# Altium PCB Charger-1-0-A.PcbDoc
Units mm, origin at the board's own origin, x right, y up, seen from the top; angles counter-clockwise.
Board outline 99.95 x 99.95 mm, 4 copper layers (Top Layer, Top GND, Bottom GND, Bottom Layer), stack 1.376 mm thick; 84 components, 44 nets, 253 pads, 194 vias.
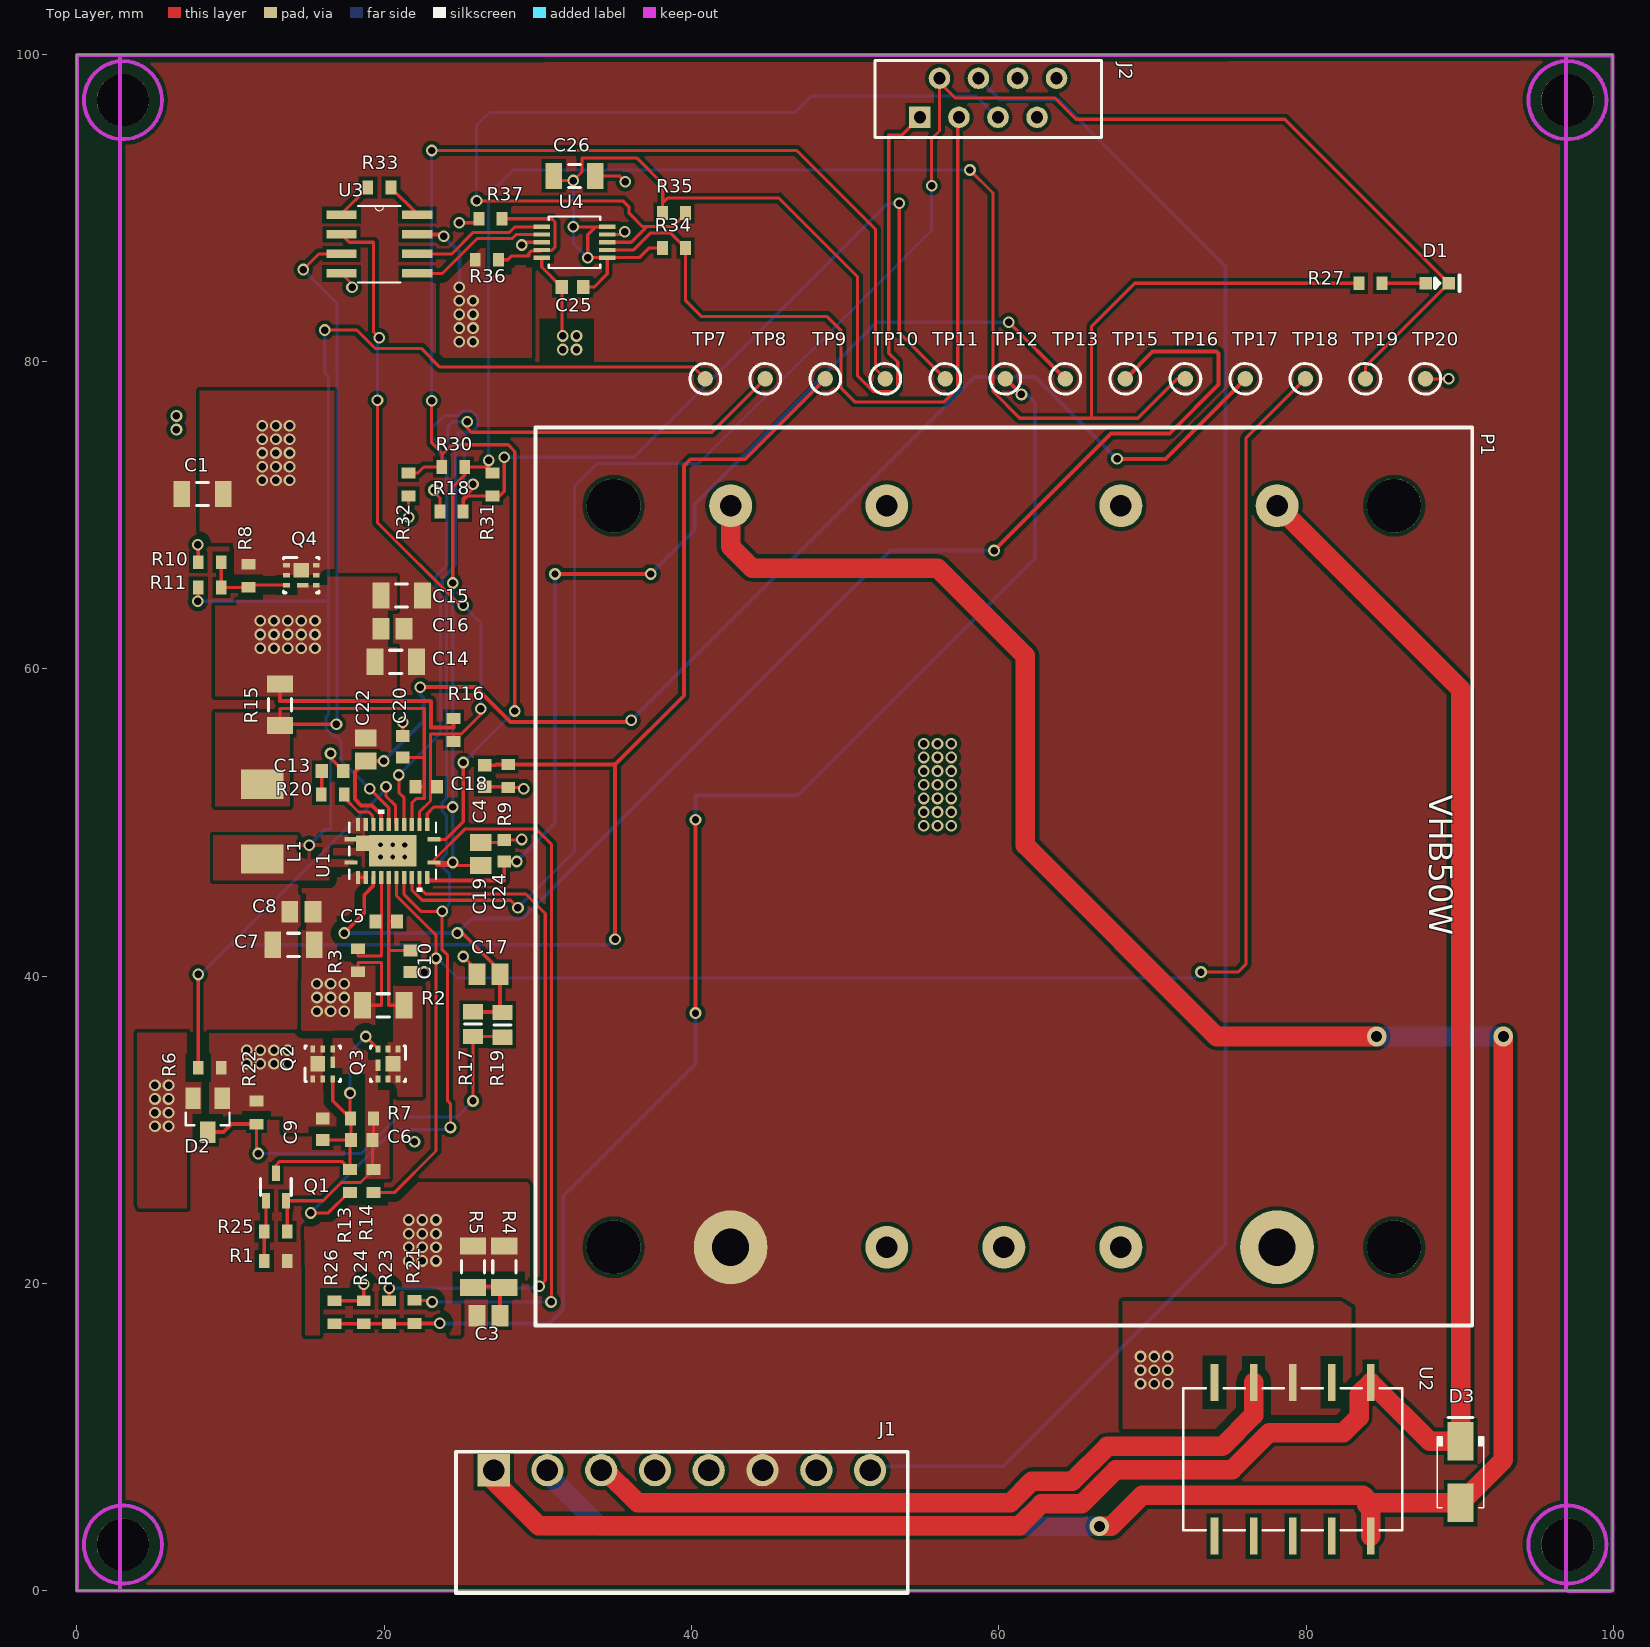
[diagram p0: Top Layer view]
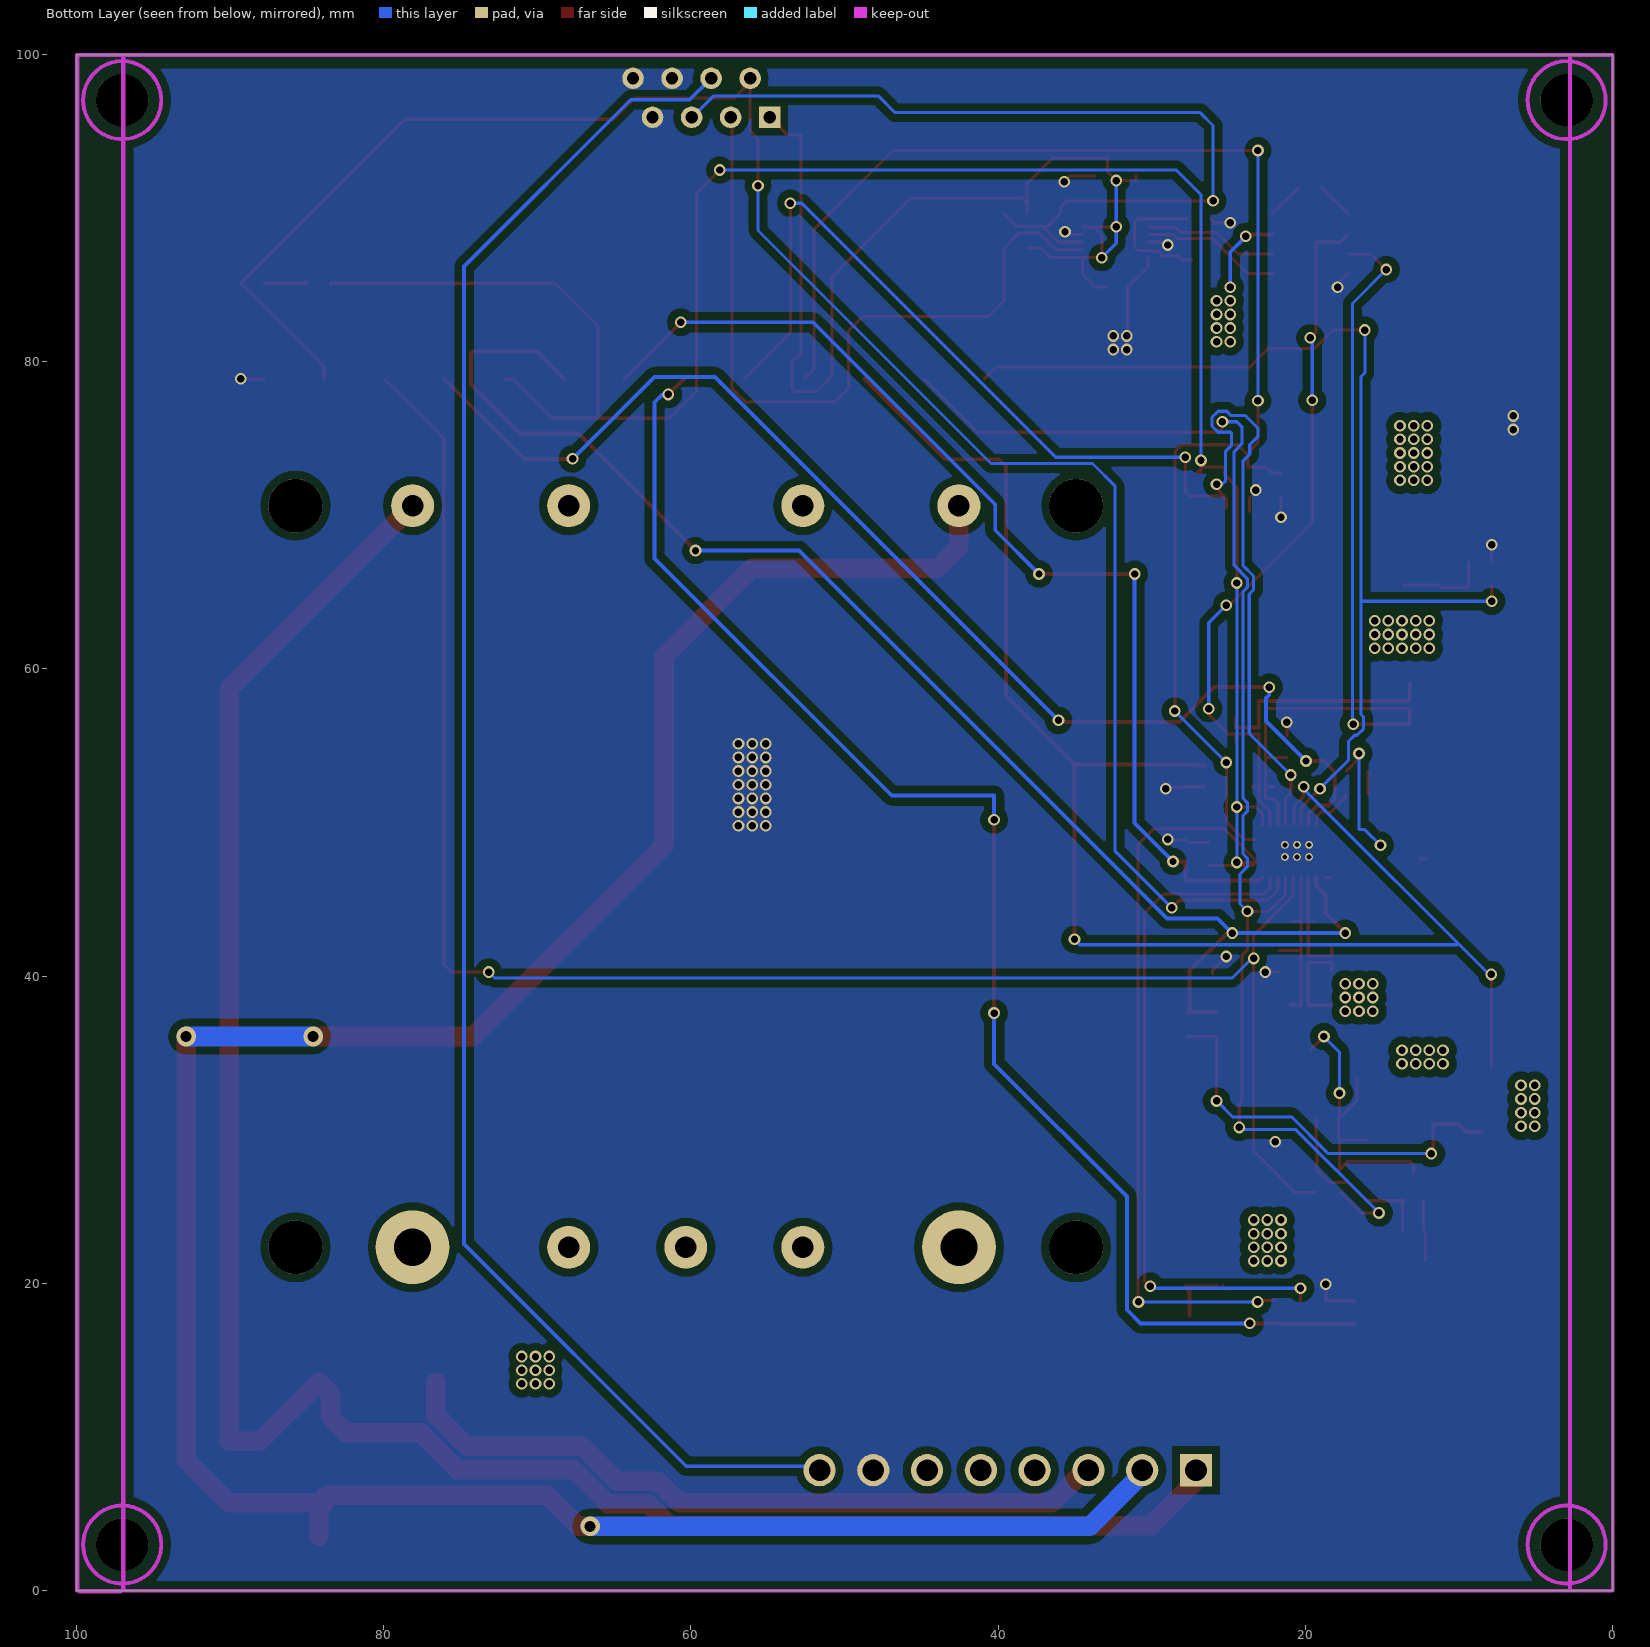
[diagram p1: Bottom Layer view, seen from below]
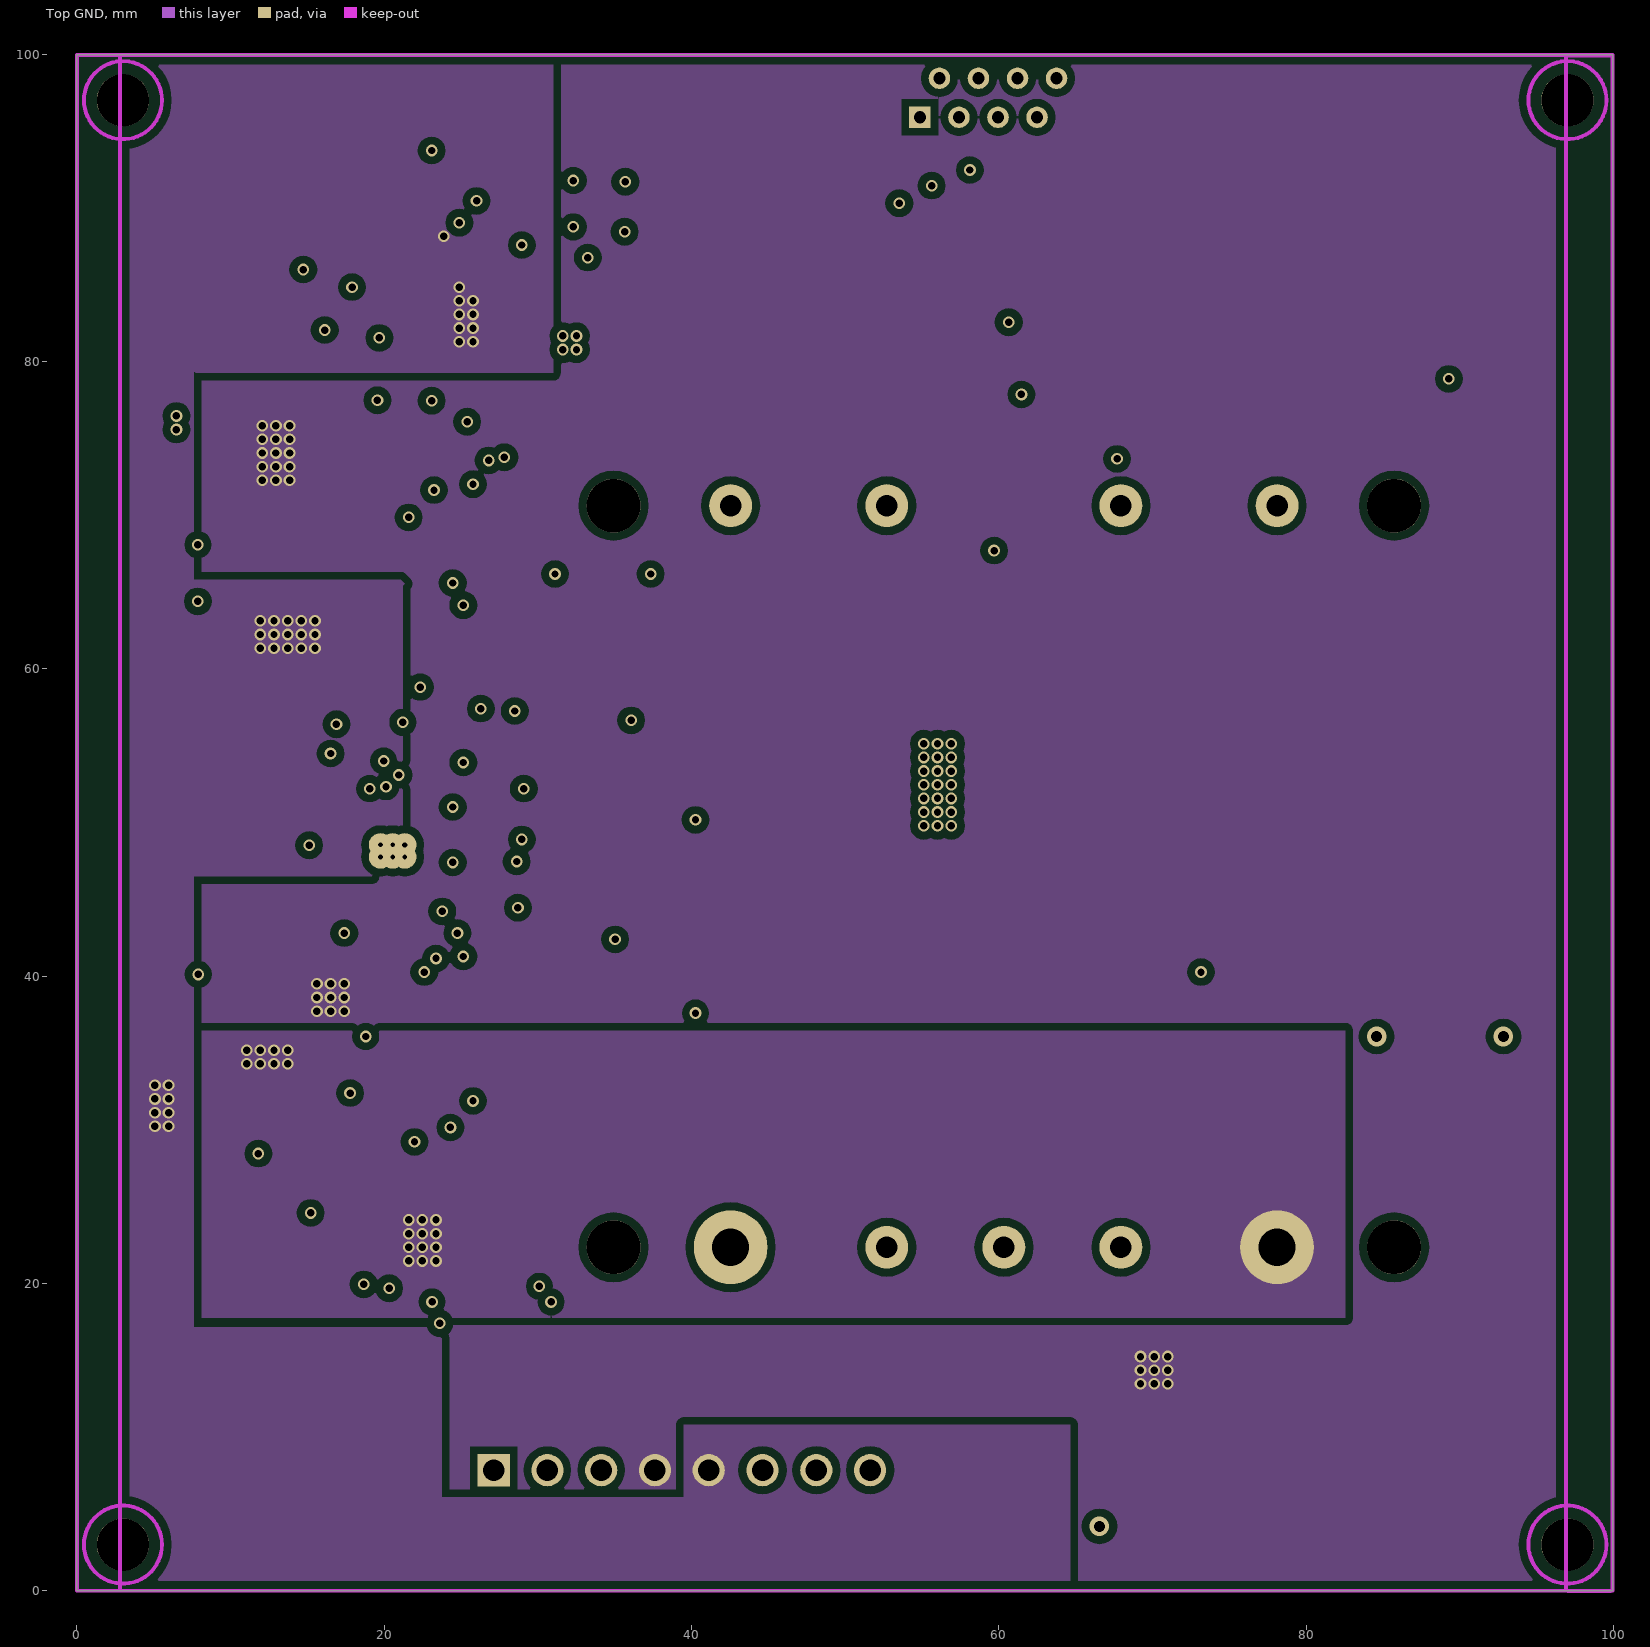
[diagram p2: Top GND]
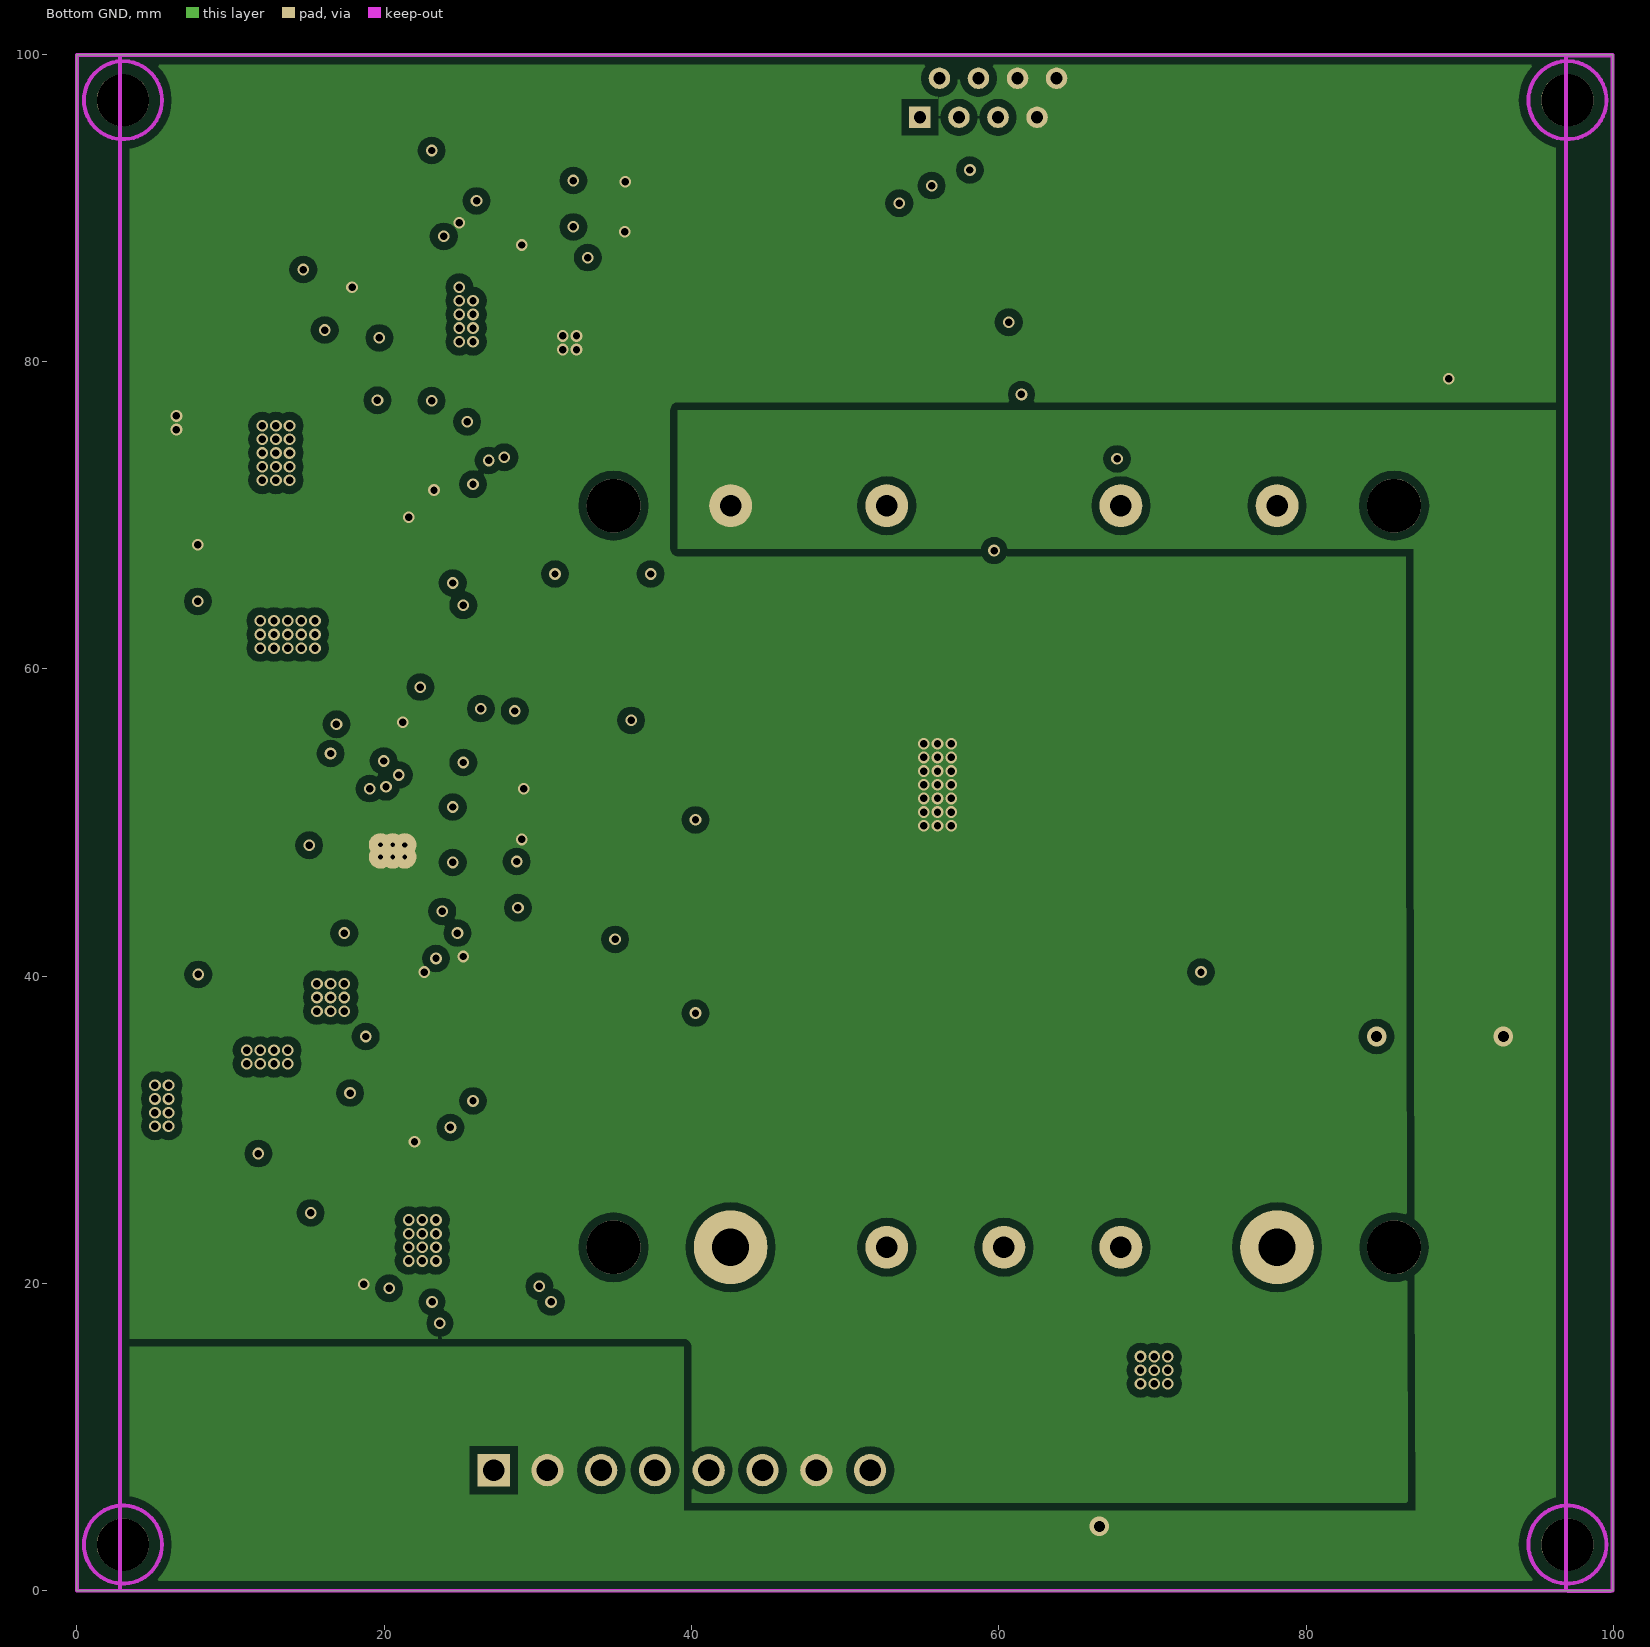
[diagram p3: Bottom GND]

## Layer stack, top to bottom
Top Layer: signal copper 0.071
Dielectric: core 0.452, FR-4, Dk 4.8
Top GND: signal copper 0.071
Dielectric: prepreg 0.32, FR-4, Dk 4.8
Bottom GND: signal copper 0.071
Dielectric: core 0.32, FR-4, Dk 4.8
Bottom Layer: signal copper 0.071

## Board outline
0,0 0,99.949 99.949,99.949 99.949,0 0,0

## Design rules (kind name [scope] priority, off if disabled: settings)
AssemblyTestPointUsage AssemblyTestPointUsage_1 [All] p2:
AssemblyTestpoint AssemblyTestpoint_1 [All] p2: testpointundercomponent=TRUE minsize=1.016 maxsize=2.54 preferedsize=1.524 minholesize=0 maxholesize=1.016 preferedholesize=0.813 testpointgrid=0.025 usegrid=TRUE gridtolerance=0 allowsidetop=TRUE allowsidebottom=TRUE
Clearance Clearance_2 [InNamedPolygon('Top Layer-AGND')] p1: gap=0.254
Clearance Clearance_1 [InPolygon] p2: gap=0.508
Clearance [All] p3: gap=0.2
ComponentClearance ComponentClearance_1 [All] p2: gap=0.254 collisioncheckmode=3 verticalgap=0.254 showdistances=FALSE
DiffPairsRouting DiffPairsRouting_1 [All] p2: maxlimit=0.254 minlimit=0.254 mostfreqgap=0.254 maxuncoupledlength=12.7
FabricationTestPointUsage TestPointUsage [All] p2: valid=0 allowmultiple=FALSE
FabricationTestpoint Testpoint [All] p2: side=3 testpointundercomponent=TRUE minsize=1.016 maxsize=2.54 preferedsize=1.524 minholesize=0 maxholesize=1.016 preferedholesize=0.813 testpointgrid=0.025 allowsidetop=TRUE allowsidebottom=TRUE usegrid=TRUE gridtolerance=0
FanoutControl Fanout_LCC [IsLCC] p1: bgadir=Out bgaviamode=Centered fanoutstyle=Auto fanoutdirection=Alternating viagrid=0.025 // Fanout_LCC (Default Rule)
FanoutControl Fanout_BGA [IsBGA] p2: bgadir=Out bgaviamode=Centered fanoutstyle=Auto fanoutdirection=Alternating viagrid=0.025 // Fanout_BGA (Default Rule)
FanoutControl Fanout_Small [(CompPinCount < 5)] p3: bgadir=Out bgaviamode=Centered fanoutstyle=Auto fanoutdirection=OutThenIn viagrid=0.025 // Fanout_Small (Default Rule)
FanoutControl Fanout_SOIC [IsSOIC] p4: bgadir=Out bgaviamode=Centered fanoutstyle=Auto fanoutdirection=Alternating viagrid=0.025 // Fanout_SOIC (Default Rule)
FanoutControl Fanout_BGA_1 [IsBGA] p6: bgadir=Out bgaviamode=Centered fanoutstyle=Auto fanoutdirection=Alternating viagrid=0.025 // Fanout_BGA (Default Rule)
FanoutControl Fanout_LCC_1 [IsLCC] p7: bgadir=Out bgaviamode=Centered fanoutstyle=Auto fanoutdirection=Alternating viagrid=0.025 // Fanout_LCC (Default Rule)
FanoutControl Fanout_SOIC_1 [IsSOIC] p8: bgadir=Out bgaviamode=Centered fanoutstyle=Auto fanoutdirection=Alternating viagrid=0.025 // Fanout_SOIC (Default Rule)
FanoutControl Fanout_Small_1 [(CompPinCount < 5)] p9: bgadir=Out bgaviamode=Centered fanoutstyle=Auto fanoutdirection=OutThenIn viagrid=0.025 // Fanout_Small (Default Rule)
FanoutControl Fanout_Default_1 [All] p10: bgadir=Out bgaviamode=Centered fanoutstyle=Auto fanoutdirection=Alternating viagrid=0.025 // Fanout_Default (Default Rule)
Height Height_1 [All] p2: minheight=0 maxheight=25.4 prefheight=12.7
HoleSize HoleSize_1 [All] p2: absolutevalues=TRUE maxlimit=2.54 minlimit=0.025 maxpercent=80.000 minpercent=20.000
HoleToHoleClearance HoleToHoleClearance_1 [All] p2: gap=0.254 allowstackedmicrovias=TRUE
LayerPairs LayerPairs_1 [All] p2: enforce=TRUE
MinimumSolderMaskSliver MinimumSolderMaskSliver_1 [All] p2: minsoldermaskwidth=0.254
NetAntennae NetAntennae_1 [All] p2: netantennaetolerance=0
PasteMaskExpansion PasteMaskExpansion_1 [All] p2: expansion=0
PlaneClearance PlaneClearance_1 [(IsFill OR IsPolygon OR IsRegion)] p1: clearance=0.508
PlaneClearance [All] p2: clearance=0.508
PolygonConnect [All vs IsNamedPolygon('Top Layer-AGND')] p1: connectstyle=Direct reliefconductorwidth=0.254 reliefentries=4 polygonreliefangle="90 Angle"
PolygonConnect PolygonConnect_Pads [All vs (InPadClass('All Pads'))] p2: connectstyle=Direct reliefconductorwidth=0.254 reliefentries=4 polygonreliefangle="90 Angle"
PolygonConnect PolygonConnect_Powerlines [All vs (InNet('12V') OR InNet('15V') OR InNet('DCGND') OR InNet('VSYS')OR InNet('GND')OR InNet('VBAT') OR InNet('AGND') OR InNet('TPST4'))] p3: connectstyle=Direct reliefconductorwidth=0.254 reliefentries=4 polygonreliefangle="90 Angle"
RoomDefinition Charger-1-0-A [InComponentClass('Charger-1-0-A')] p1: confinementstyle=ConfineIn formatcopy=TRUE lockcomponents=FALSE outline -22.733,-25.781 28.067,-25.781 28.067,-0.381 -22.733,-0.381
RoomDefinition Mini_Charger_Sensor [InComponentClass('Mini_Charger_Sensor')] p2: confinementstyle=ConfineIn formatcopy=TRUE lockcomponents=FALSE outline -22.733,-25.781 28.067,-25.781 28.067,-0.381 -22.733,-0.381
RoutingLayers [All] p1: top layer_v5=TRUE mid layer 1_v5=FALSE mid layer 2_v5=FALSE bottom layer_v5=TRUE
RoutingPriority RoutingPriority_1 [All] p2: routingpriority=0
RoutingTopology RoutingTopology_1 [All] p2: topology=Shortest
RoutingVias [All] p1: holewidth=0.483 width=0.762 viastyle="Through Hole" minholewidth=0.483 minwidth=0.762 maxholewidth=0.483 maxwidth=0.762
SMDNeckDown [All] p1: percent=50.000
SilkToSilkClearance SilkToSilkClearance_1 [All] p2: silktosilkclearance=0.254
SilkscreenOverComponentPads [All] p1: minsilkscreentomaskgap=0.254
SilkscreenOverComponentPads SilkscreenOverComponentPads_1 [All] p2: minsilkscreentomaskgap=0.254
SolderMaskExpansion [All] p1: expansion=0.102
SolderMaskExpansion SolderMaskExpansion_1 [All] p2: expansion=0.102
Width Width_1 [(InNet('12V') OR InNet('DCGND') OR InNet('TPST4'))] p1: maxlimit=1.27 minlimit=1.27 preferedwidth=1.27
Width [All] p2: maxlimit=0.254 minlimit=0.203 preferedwidth=0.254
21 further rules are at their usual default settings.

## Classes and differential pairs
component class Mini_Charger_Sensor: C25 C26 D3 J1 J2 P1 R33 R34 R35 R36 R37 U2 U3 U4
component class Charger-1-0-A: C1 C3 C4 C5 C6 C7 C8 C9 C10 C13 C14 C15 C16 C17 C18 C19 C20 C22 C24 D1 D2 L1 Q1 Q2 Q3 Q4 R1 R2 R3 R4 R5 R6 R7 R8 R9 R10 R11 R13 R14 R15 R16 R17 R18 R19 R20 R21 R22 R23 R24 R25 R26 R27 R30 R31 R32 TP7 TP8 TP9 TP10 TP11 TP12 TP13 TP15 TP16 TP17 TP18 TP19 TP20 U1 ""

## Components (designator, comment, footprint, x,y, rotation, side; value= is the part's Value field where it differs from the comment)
C1 "" CAPC3216L 8.175,71.374 r180 top
C3 "" CAPC2012L 26.785,17.907 r0 top
C4 "" CAPC1608L 26.543,53.021 r90 top
C5 "" CAPC1608L 20.128,43.561 r0 top
C6 "" CAPC1608L 18.542,29.337 r0 top
C7 "" CAPC3216L 14.097,42.037 r0 top
C8 "" CAPC2012L 14.605,44.196 r0 top
C9 "" CAPC1608L 16.002,30.034 r90 top
C10 "" CAPC1608L 21.717,40.959 r90 top
C13 "" CAPC1608L 16.637,53.34 r0 top
C14 "" CAPC3216L 20.748,60.452 r180 top
C15 "" CAPC3216L 21.129,64.77 r180 top
C16 "" CAPC2012L 20.529,62.611 r180 top
C17 "" CAPC2012L 26.785,40.132 r180 top
C18 "" CAPC1608L 22.733,52.324 r0 top
C19 "" CAPC2012L 26.289,47.954 r270 top
C20 "" CAPC1608L 21.209,54.926 r270 top
C22 "" CAPC2012L 18.796,54.749 r270 top
C24 "" CAPC1608L 27.813,48.154 r270 top
C25 "" CAPC1608L 32.258,84.836 r0 top
C26 "" CAPC3216L 32.385,92.075 r180 top
D1 "LTST-C190GKT" "Lite on LED" 87.781,85.09 r0 top
D2 "BAT54C" SOT23 8.509,30.945 r180 top
D3 "MRA4004T3G" "SMA Diodes Inc" 90.043,7.715 r90 top
J1 "691322110008" 691322110008 39.37,4.445 r0 top
J2 "Female, 08p" 690368190872 59.309,97.155 r0 top
J3 "2 way net tie junction" 2way_MP 19.431,48.641 r0 top net-tie
L1 "IHLP2020CZER3R3M" Inductor 12.065,52.476 r270 top
P1 "VHB50W-Q24-S15" VHB50W 42.545,70.612 r270 top
Q1 "BSS138W" SOT323 12.954,26.278 r0 top
Q2 "CSD17313Q2" DQK0006C 16.002,34.29 r90 top
Q3 "CSD17313Q2" DQK0006C 20.249,34.29 r270 top
Q4 "CSD25302Q2" DQK0006C 14.605,66.096 r0 top
R1 "Res Semi" RESC1608L 12.942,21.463 r0 top
R2 "Res Semi" RESC3216L 19.939,38.1 r0 top
R3 "Res Semi" RESC1608L 18.288,41.033 r270 top
R4 "Res Semi" RESC3216L 27.813,21.082 r90 top
R5 "Res Semi" RESC3216L 25.781,21.082 r90 top
R6 "Res Semi" RESC1608L 8.648,34.036 r0 top
R7 "Res Semi" RESC1608L 18.554,30.734 r0 top
R8 "Res Semi" RESC1608L 11.176,66.052 r90 top
R9 "Res Semi" RESC1608L 28.067,53.021 r90 top
R10 "Res Semi" RESC1608L 8.648,66.929 r180 top
R11 "Res Semi" RESC1608L 8.648,65.278 r0 top
R13 "Res Semi" RESC1608L 17.78,26.658 r90 top
R14 "Res Semi" RESC1608L 19.304,26.658 r90 top
R15 "Res Semi" RESC3216L 13.208,57.658 r270 top
R16 "Res Semi" RESC1608L 24.511,56.019 r90 top
R17 "Res Semi" RESC2012L 25.781,36.868 r270 top
R18 "Res Semi" RESC1608L 24.384,70.231 r0 top
R19 "Res Semi" RESC2012L 27.686,36.83 r270 top
R20 "Res Semi" RESC1608L 16.649,51.816 r180 top
R21 "Res Semi" RESC1608L 21.971,18.149 r90 top
R22 "Res Semi" RESC1608L 11.684,31.115 r90 top
R23 "Res Semi" RESC1608L 20.32,18.125 r270 top
R24 "Res Semi" RESC1608L 18.669,18.125 r270 top
R25 "Res Semi" RESC1608L 12.942,23.368 r180 top
R26 "Res Semi" RESC1608L 16.764,18.125 r270 top
R27 "Res Semi" RESC1608L 84.189,85.09 r180 top
R30 "Res Semi" RESC1608L 24.499,73.128 r0 top
R31 "Res Semi" RESC1608L 27.051,71.997 r90 top
R32 "Res Semi" RESC1608L 21.59,71.997 r90 top
R33 "Res Semi" RESC1608L 19.685,91.313 r180 top
R34 "Res Semi" RESC1608L 38.862,87.376 r180 top
R35 "Res Semi" RESC1608L 38.862,89.662 r180 top
R36 "Res Semi" RESC1608L 26.682,86.614 r180 top
R37 "Res Semi" RESC1608L 26.912,89.281 r0 top
TP7 "Test Point" PAD1 40.894,78.867 r0 top
TP8 "Test Point" PAD1 44.799,78.867 r0 top
TP9 "Test Point" PAD1 48.704,78.867 r0 top
TP10 "Test Point" PAD1 52.61,78.867 r90 top
TP11 "Test Point" PAD1 56.515,78.867 r90 top
TP12 "Test Point" PAD1 60.42,78.867 r90 top
TP13 "Test Point" PAD1 64.325,78.867 r90 top
TP15 "Test Point" PAD1 68.231,78.867 r90 top
TP16 "Test Point" PAD1 72.136,78.867 r90 top
TP17 "Test Point" PAD1 76.041,78.867 r90 top
TP18 "Test Point" PAD1 79.947,78.867 r90 top
TP19 "Test Point" PAD1 83.852,78.867 r90 top
TP20 "Test Point" PAD1 87.757,78.867 r90 top
U1 "BQ24133RHL" RGY24_2P05X3P1 20.549,48.146 r90 top locked
U2 "TQ2SA-12V" RELAY_TQ2_SA 79.134,8.56 r270 top
U3 "AD620ARZ" SOIC127P600X175-8N 19.685,87.63 r0 top
U4 "MCP3427" MSOP-10_MS-L 32.385,87.757 r0 top

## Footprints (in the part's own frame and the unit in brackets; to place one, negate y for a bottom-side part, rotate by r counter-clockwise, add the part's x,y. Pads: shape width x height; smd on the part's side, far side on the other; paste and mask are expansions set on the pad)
2way_MP [mil] "2 way medium power net tie junction"
  rrect5% 40x40 smd paste-100: 1(-30,0) 2(30,0)
690368190872 [mm] "Female Connector, THT, Angled, 08p"
  rect 1.4x1.4 hole 0.8: 1(-4.445,-1.27)
  round 1.4 hole 0.8: 2(-3.175,1.27) 3(-1.905,-1.27) 4(-0.635,1.27) 5(0.635,-1.27) 6(1.905,1.27) 7(3.175,-1.27) 8(4.445,1.27)
  silkscreen extent -7.38,-2.58 7.38,2.42, body extent -7.38,-2.58 7.38,2.42, height 5.85
691322110008 [mm] "Horizontal PCB Header, pitch 3.5mm, 08p"
  rect 2.1x2.1 hole 1.4: 1(-12.25,3.4)
  round 2.1 hole 1.4: 2(-8.75,3.4) 3(-5.25,3.4) 4(-1.75,3.4) 5(1.75,3.4) 6(5.25,3.4) 7(8.75,3.4) 8(12.25,3.4)
  silkscreen extent -14.7,-4.6 14.7,4.6, body extent -14.7,-4.6 14.7,4.6, height 7.3
CAPC1608L [mm] "Chip Capacitor, Body 1.6x0.8mm, IPC High Density"
  rect 0.8x0.9 smd: 1(-0.7,0) 2(0.7,0)
  body extent -0.87,-0.48 0.87,0.48, height 1.3
CAPC2012L [mm] "Chip Capacitor, Body 2.0x1.3mm, IPC High Density"
  rect 1.1x1.4 smd: 1(-0.75,0) 2(0.75,0)
  body extent -1.1,-0.72 1.1,0.72, height 1.4
CAPC3216L [mm] "Chip Capacitor, Body 3.2x1.6mm, IPC High Density"
  rect 1.1x1.7 smd: 1(-1.35,0) 2(1.35,0)
  silkscreen extent -0.4,-0.75 0.4,0.75, body extent -1.7,-0.9 1.7,0.9, height 1.3
DQK0006C [mm]
  rect 0.45x0.3 smd paste+0 mask+0.051: 1(-0.975,0.65) 2(-0.975,0) 3(-0.975,-0.65) 4(0.975,-0.65) 5(0.975,0) 6(0.975,0.65)
  rect 0.75x0.3 smd paste-0.362 mask+0.051: 7(0.095,-0.65)
  rect 1x0.95 smd paste-0.487 mask+0.051: 8(0,0.325)
  silkscreen extent -1.15,-1.15 1.15,1.15
Inductor [mil] "IHLP2020CZER3R3M01"
  rect 75x110 smd: 1(0,0) 2(191,0)
"Lite on LED" [mm]
  rect 0.8x0.8 smd: 1(0,0) 2(1.5,0)
  silkscreen extent 0.6,-0.5 2.2,0.5, body extent -0.2,-0.4 1.7,0.4, height 0.8
MSOP-10_MS-L [mil]
  rect 43x11 smd paste-1000 mask-1000: 1(-84,39.4) 2(-84,19.7) 3(-84,0) 4(-84,-19.7) 5(-84,-39.4) 6(84,-39.4) 7(84,-19.7) 8(84,0) 9(84,19.7) 10(84,39.4)
  silkscreen extent -66,-66 66,66
PAD1 [mm] "Connector; Pad"
  round 1 smd: 1(0,0)
  silkscreen extent -1,-1 1,1
RELAY_TQ2_SA [mil]
  rect 95x20 smd: 1(-197,199.5) 2(-197,99.5) 3(-197,-0.5) 4(-197,-100.5) 5(-197,-200.5) 6(197,-200.5) 7(197,-100.5) 8(197,-0.5) 9(197,99.5) 10(197,199.5)
  silkscreen extent -182,-281 182,281
RESC1608L [mm] "Chip Resistor, Body 1.6x0.8mm, IPC High Density"
  rect 0.7x0.9 smd: 1(-0.75,0) 2(0.75,0)
  body extent -0.85,-0.48 0.85,0.48, height 0.9
RESC2012L [mm] "Chip Resistor, Body 2.0x1.3mm, IPC High Density"
  rect 1x1.3 smd: 1(-0.8,0) 2(0.8,0)
  silkscreen extent 0,-0.55 0,0.55, body extent -1.07,-0.7 1.07,0.7, height 2.54
RESC3216L [mm] "Chip Resistor, Body 3.1x1.6mm, IPC High Density"
  rect 1.1x1.7 smd: 1(-1.35,0) 2(1.35,0)
  silkscreen extent -0.4,-0.75 0.4,0.75, body extent -1.68,-0.87 1.68,0.87, height 2.54
RGY24_2P05X3P1 [mm]
  rect 0.28x0.85 smd paste-0.14: 1(-0.75,2.696) 12(-0.75,-2.696) 13(0.75,-2.696) 24(0.75,2.696)
  rect 0.85x0.28 smd paste-0.14: 2(-1.731,2.25) 3(-1.731,1.75) 4(-1.731,1.25) 5(-1.731,0.75) 6(-1.731,0.25) 7(-1.731,-0.25) 8(-1.731,-0.75) 9(-1.731,-1.25) 10(-1.731,-1.75) 11(-1.731,-2.25) 14(1.731,-2.25) 15(1.731,-1.75) 16(1.731,-1.25) 17(1.731,-0.75) 18(1.731,-0.25) 19(1.731,0.25) 20(1.731,0.75) 21(1.731,1.25) 22(1.731,1.75) 23(1.731,2.25)
  rect 2.05x3.1 smd paste-1.537 mask-1.537: 25(0,0)
  round 0.508 / inner round 1.524 / far side round 0.508 hole 0.305: V(-0.394,0.787) V(-0.394,0) V(-0.394,-0.787) V(0.394,0.787) V(0.394,0)
  round 0.508 / inner round 1.524 / far side round 0.508 hole 0.33: V(0.394,-0.787)
  Top Layer region: 0,1.55 0,1.55 0,1.55 0,1.55 0,1.55 0,1.55 0,1.55 0,1.55
  Top Layer region: 0,-1.55 0,-1.55 0,-1.55 0,-1.55 0,-1.55 0,-1.55 0,-1.55 0,-1.55
  silkscreen extent -2.66,-2.82 2.66,2.82
"SMA Diodes Inc" [mm] "Molded Diode, SMA Package for Diodes Inc schottky rectifier"
  rect 2.5x1.7 smd: 1(-2,0) 2(2,0)
  silkscreen extent -2.3,-1.55 3.55,1.55, body extent -2.3,-1.46 2.3,1.46, height 2.3
SOIC127P600X175-8N [mil]
  rect 78x22 smd paste-1000 mask-1000: 1(-97,75) 2(-97,25) 3(-97,-25) 4(-97,-75) 5(97,-75) 6(97,-25) 7(97,25) 8(97,75)
  silkscreen extent -54,-98 54,98
SOT23 [mm]
  rect 1x1.4 smd paste-25.4 mask-25.4: 1(-0.95,-1.1) 2(0.95,-1.1) 3(0,1.1)
  silkscreen extent -1.42,-0.15 1.42,0.66
SOT323 [mm]
  rect 0.5x1 smd paste-25.4 mask-25.4: 1(-0.65,-0.9) 2(0.65,-0.9) 3(0,0.9)
  silkscreen extent -1,-0.55 1,0.55
VHB50W [mil] "DC_DC_Convertor"
  round 110 hole 55: 1(0,0) 2(0,400) 3(0,1000) 4(0,1400) 6(1900,1000) 7(1900,700) 8(1900,400)
  round 189 hole 95: 5(1900,1400) 9(1900,0)
  round 138 hole 138: ""(0,1700) ""(0,-300) ""(1900,1700) ""(1900,-300)
  silkscreen extent -200,-500 2100,1900, body extent -190,-510 2110,1890, height 500

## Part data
C1 C3 C7 C8 C9 C14 C15 C16 C17 C25 C26: library part "Cap Semi", "Capacitor, Ceramic, 25V, X7R, 10%"
C4 C6 C10 C13 C20 C24: library part "Cap Semi", "Capacitor, Ceramic, 50V, X7R, 10%"
C5 C18: library part "Cap Semi", "Capacitor, Ceramic, 16V, X7R, 10%"
C19 C22: library part "Cap Semi", "Capacitor, Ceramic, 16V, X7R, 20%"
D1: library part LED, "LED Green, 2.1V, 20mA, 6mcd"
D2: "BAT54 Series 30 V 600 mA Surface Mount Schottky Barrier Diode - SOT-23"
D3: library part "Diode Diodes Inc.", "Schottky Rectifier"
J1: "WR-TBL Serie 3221 - 3.50 mm Horizontal PCB Header, 08p"
J2: library part "WR-MM, 690368190872", "WR-MM Female Angled Connector with Latch and with Polarization, 08p"
J3: library part 2way
P1: library part DC_DC, "DC DC Converter 15V"
Q4: library part CSD17313Q2
R1 R10 R17 R19 R23 R26: "Resistor, Chip, 1/16W, 5%"
R2: "Resistor, Chip, 1/2W, 1%"
R3 R16 R20 R22: "Resistor, Chip, 1/16W"
R4 R5: "Resistor,Chip, 1/4W, 5 %"
R6 R8 R9 R11 R13 R14 R18 R21 R24 R25 R27 R30 R31 R32 R34 R35 R36 R37: "Resistor, Chip, 1/16W, 1%"
R7: "Resistor, Chip, 1/8W, 1%"
R15: "Resistor, Metal Film, 1/2W, 1%"
R33: "Resistor, Chip, 1/16W, 0.1%"
U1: library part BQ24133_RGY_24
U3: library part AD620ARZ-REEL7
U4: library part MCP3427-E/MF

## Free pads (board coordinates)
  round 3.4 hole 3.4: 0(3,3) 1(97,3) 2(97,97) 3(3,97)

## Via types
v1: diameter 0.762, hole 0.483, Top Layer to Bottom Layer, tented both sides, 119 vias
v2: diameter 0.762, hole 0.483, Top Layer to Bottom Layer, 71 vias
v3: diameter 1.27, hole 0.711, Top Layer to Bottom Layer, 3 vias
v4: diameter 0.762, hole 0.483, Top Layer to Bottom Layer, tented bottom, 1 vias

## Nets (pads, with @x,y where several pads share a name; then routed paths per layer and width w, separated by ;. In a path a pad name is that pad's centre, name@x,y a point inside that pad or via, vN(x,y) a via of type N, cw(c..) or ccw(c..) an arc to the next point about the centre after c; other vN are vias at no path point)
3V3D: C25.2 C26.2 J2.1 R34.2 R35.2 U4.6 U4.10 | length 72.8
  Top Layer w0.203: C26.2 31.035,91.77 v1(32.309,91.77) 32.868,92.329 32.868,93.243 36.424,93.243 38.125,91.542 38.125,90.322 ; v2(32.309,88.758) 33.757,88.758 ; C25.2 33.655,84.836 34.519,85.7 U4.6 ; U4.10 33.757,88.758 ; R35.2 38.112,90.309 38.125,90.322 ; R34.2@38.125,87.376 R34.2 37.211,87.376 36.591,86.756 U4.6 ; J2.1 53.721,94.742 52.832,94.742 52.832,80.543 53.416,79.959 53.416,78.257 53.213,78.054 51.816,78.054 50.8,79.07 50.8,85.522 45.695,90.627 38.43,90.627 38.125,90.322 ; 33.757,88.758 33.249,88.25 v2(33.249,86.756) U4.6
  Bottom Layer w0.203: v1(32.309,91.77) v2(32.309,88.758) 32.309,87.696 v2(33.249,86.756)
12V: D3.2 J1.1 P1.4 U2.1 | length 137.3
  Top Layer w1.27: J1.1@27.12,8.099 J1.1 27.12,7.17 30.045,4.245 61.348,4.245 62.764,5.661 65.398,5.661 67.611,7.874 75.184,7.874 77.597,10.287 82.423,10.287 83.439,11.303 83.439,12.802 U2.1 ; P1.4 90.043,58.674 D3.2 88.05,9.715 U2.1 ; U2.1@84.201,13.462 U2.1
15V: C9.2 D2.1 P1.5 Q2.1 Q2.2 Q2.5 Q2.6 Q2.8 R4.2 R5.2 R6.2 R22.2
  other v1: 21.59,21.463 22.479,21.463 23.368,21.463 21.59,22.352 22.479,22.352 23.368,22.352 21.59,23.241 22.479,23.241 23.368,23.241 21.59,24.13 22.479,24.13 23.368,24.13 11.049,34.29 11.938,34.29 12.827,34.29 13.716,34.29 11.049,35.179 11.938,35.179 12.827,35.179 13.716,35.179
AGND: C1.2 C3.1 C7.1 C8.1 C14.1 C15.1 C16.1 C22.1 J1.6 J3.1 P1.9 R1.2 U1.22 U1.23
DCGND: D3.1 J1.2 P1.1 U2.10 | length 169.2
  Top Layer w1.27: P1.1 42.545,67.945 43.942,66.548 56.007,66.548 61.722,60.833 61.722,48.514 74.168,36.068 v3(84.582,36.068) ; v3(66.548,4.191) 67.31,4.191 69.342,6.223 83.693,6.223 84.201,5.715 D3.1 92.837,8.509 v3(92.837,36.068) ; 83.938,5.597 84.201,5.334 U2.10
  Bottom Layer w1.27: J1.2 30.62,7.607 34.036,4.191 v3(66.548,4.191) ; v3(84.582,36.068) v3(92.837,36.068)
GND: C4.1 C10.1 C17.2 C19.1 C20.1 C24.1 C25.1 C26.1 J1.7 J2.6 J2.7 J2.8 J3.2 R9.1 R10.2 R18.1 R24.1 R26.1 R32.1 R37.1 TP20.1 U1.25 U1.V U3.4 U4.3 U4.5 U4.9 | length 30.2
  Top Layer w0.203: v1(7.874,68.072) 7.898,68.048 R10.2 ; R26.1 R24.1 v2(18.669,19.939) ; U3.4 17.907,85.039 v1(17.907,84.836) ; C20.1 v1(21.209,56.515) ; v1(21.59,69.85) R32.1 ; C10.1 v2(22.606,40.259) ; v2(23.241,71.628) 23.241,71.501 23.634,71.108 R18.1 ; v1(24.892,89.027) 25.908,89.027 R37.1 ; v1(25.146,41.275) 26.035,40.386 C17.2 ; C19.1 27.663,48.704 C24.1 28.915,48.854 v2(28.956,48.895) ; C4.1 28.017,52.321 R9.1 29.009,52.271 v2(29.083,52.197) ; v2(28.956,87.575) 29.138,87.757 U4.3 ; U4.5 30.251,86.143 C25.1 31.558,81.726 v1(31.623,81.661) ; C26.1 35.306,92.075 v1(35.687,91.694) ; U4.9 35.463,88.257 v2(35.646,88.44) ; TP20.1 v2(89.281,78.867)
  Top GND w0.203: v2@28.901,87.63 v2(28.956,87.575)
  Bottom Layer w0.203: v2@35.608,88.44 v2(35.646,88.44)
  other v1: 21.971,29.21 55.118,49.784 56.007,49.784 56.896,49.784 55.118,50.673 56.007,50.673 56.896,50.673 55.118,51.562 56.007,51.562 56.896,51.562 55.118,52.451 56.007,52.451 56.896,52.451 55.118,53.34 56.007,53.34 56.896,53.34 55.118,54.229 56.007,54.229 56.896,54.229 55.118,55.118 56.007,55.118 56.896,55.118 6.477,75.565 6.477,76.454 31.623,80.772 32.512,80.772 32.512,81.661
NetC3_2: C3.2 R4.1 R5.1 | length 4.4
  Top Layer w0.203: R5.1@25.146,19.605 R5.1@25.4,19.859
  Top Layer w0.254: R5.1@25.781,19.812 27.813,19.812 27.535,19.534 C3.2
NetC4_2: C4.2 R6.1 R9.2 TP9.1 U1.18 | length 103.9
  Top Layer w0.203: R6.1 v2(7.898,40.108) ; v2(20.114,52.324) 20.114,51.703 20.74,51.077 20.74,49.935 U1.18
  Top Layer w0.254: C4.2 27.254,53.721 27.304,53.771 R9.2 35.026,53.771 ; v2(35.026,42.392) 35.026,53.771 ; TP9.1 43.472,73.635 39.929,73.635 39.497,73.203 39.497,58.242 35.026,53.771
  Bottom Layer w0.203: v2(7.898,40.108) 8.053,40.108 20.114,52.169 v2(20.114,52.324)
  Bottom Layer w0.254: 10.16,42.037 34.671,42.037 v2(35.026,42.392)
NetC5_1: C5.1 R3.1 U1.5 | length 7.2
  Top Layer w0.203: R3.1 18.288,41.297 19.812,41.297 19.812,46.401 U1.5 U1.5@19.854,46.415 ; C5.1 C5.1@19.431,43.561
NetC5_2: C5.2 C10.2 Q3.1 Q3.2 Q3.5 Q3.6 Q3.8 R2.2 U1.6 | length 11.2
  Top Layer w0.203: U1.6 20.299,45.707 20.299,44.29 20.299,43.582 ; R2.2@20.828,38.26 20.988,38.1 20.299,38.1 20.299,38.994 20.299,40.783 20.299,41.677 ; C5.2 20.32,43.561 20.299,43.582 ; C10.2 21.714,41.656 20.32,41.656 20.299,41.677 ; 20.299,41.677 20.299,43.582
NetC6_1: C6.1 C9.1 Q1.3 Q2.3 Q3.3 R7.1 R13.2 | length 20.8
  Top Layer w0.203: Q1.3 12.954,27.686 13.208,27.94 17.248,27.94 R13.2 17.78,29.275 C6.1 ; C9.1 17.839,29.334 17.839,30.699 R7.1 R7.1@17.78,30.758 ; Q2.3 16.652,31.886 R7.1@17.78,30.758 ; v2(17.78,32.385) R7.1@17.78,30.758 ; v2(18.796,36.068) Q3.3
  Bottom Layer w0.203: v2(17.78,32.385) 17.78,35.052 v2(18.796,36.068)
NetC6_2: C6.2 Q1.2 Q2.4 Q2.7 Q3.4 Q3.7 R7.2 R14.2 R25.1 | length 12.1
  Top Layer w0.203: R25.1 13.692,25.29 Q1.2 16.019,25.378 17.204,26.563 18.459,26.563 R14.2 19.242,27.47 C6.2 ; R7.2 C6.2@19.304,29.399 ; C6.2 C6.2@19.304,29.399 ; C6.2 C6.2@19.304,29.399
NetC13_1: C13.1 R20.2 | length 1.5
  Top Layer w0.203: R20.2 15.937,51.854 C13.1
NetC13_2: C13.2 L1.2 U1.1 U1.24 | length 8.8
  Top Layer w0.203: L1.2 L1.2@12.573,47.625 ; v2(16.51,54.483) 16.51,54.167 C13.2
  Bottom Layer w0.203: v2(15.113,48.514) 16.129,49.53 16.51,49.53 v2(16.51,54.483)
NetC17_1: C17.1 R17.1 R19.1 TP15.1 U1.4 | length 93.4
  Top Layer w0.254: v2(17.399,42.799) 18.701,44.101 18.701,45.29 19.266,45.854 19.266,46.382 U1.4 ; v2(24.765,42.799) 25.08,42.799 27.535,40.344 C17.1 R19.1@27.535,37.668 ; R17.1 R19.1@27.535,37.668 ; R19.1 R19.1@27.546,37.63 ; v2(59.69,67.691) 67.31,75.311 71.12,75.311 74.295,78.486 74.295,80.518 74.168,80.645 70.009,80.645 TP15.1 ; R19.1@27.535,37.668 27.546,37.668 R19.1@27.546,37.63 ; R19.1@27.535,37.668 27.535,37.63 R19.1@27.546,37.63
  Bottom Layer w0.254: v2(17.399,42.799) v2(24.765,42.799) 25.708,43.742 28.995,43.742 52.944,67.691 v2(59.69,67.691)
NetC18_1: C18.1 C20.2 L1.1 R15.2 U1.16 U3.3 | length 57.7
  Top Layer w0.203: v2(14.732,85.979) 15.748,86.995 U3.3 ; v2(16.891,56.388) 13.208,56.388 13.208,57.404 22.606,57.404 22.606,54.229 ; C20.2 21.212,54.229 22.606,54.229 ; U1.16 21.799,51.263 22.098,51.562 22.606,51.562 22.606,52.324 ; C18.1 22.606,52.324 ; 22.606,52.324 22.606,54.229
  Bottom Layer w0.203: v2(14.732,85.979) 16.939,83.772 16.939,56.436 v2(16.891,56.388)
NetC18_2: C18.2 R16.1 U1.15 U3.2 | length 47.2
  Top Layer w0.203: U3.2 17.729,87.757 19.304,87.757 19.304,81.915 v2(19.685,81.534) ; v2(19.558,77.47) 19.558,69.52 24.943,64.135 v2(25.146,64.135) ; U1.15 22.299,50.684 23.009,51.395 23.009,52.324 ; C18.2 23.009,52.324 ; R16.1 24.511,55.753 ; v2(26.289,57.404) 26.289,57.023 25.019,55.753 24.511,55.753 ; 23.009,52.324 23.009,55.753 24.511,55.753
  Bottom Layer w0.203: v2@19.685,77.343 v2(19.558,77.47) 19.558,81.407 v2(19.685,81.534) ; v2(25.146,64.135) 26.289,62.992 v2(26.289,57.404)
NetC22_2: C22.2 TP17.1 U1.20 | length 81.2
  Top Layer w0.254: U1.20 19.799,50.525 19.216,51.108 18.503,51.108 18.088,51.523 18.088,53.291 C22.2 v2(19.963,53.999) ; v2(22.352,58.801) 25.948,58.801 28.206,56.544 36.166,56.544 v2(36.068,56.642) ; v2(67.691,73.66) 70.834,73.66 TP17.1
  Bottom Layer w0.254: v2(19.963,53.999) 22.558,56.594 22.558,58.087 22.352,58.293 v2(22.352,58.801) ; v2(36.068,56.642) 58.42,78.994 62.357,78.994 v2(67.691,73.66)
NetC24_2: C24.2 TP13.1 U1.11 | length 69.4
  Top Layer w0.254: U1.11 22.985,46.228 27.813,46.228 C24.2 v2(28.619,47.454) ; v2(31.115,66.167) v2(37.338,66.167) ; v2(60.642,82.55) TP13.1
  Bottom Layer w0.254: v2(28.619,47.454) 31.115,49.95 v2(31.115,66.167) ; v2(37.338,66.167) 40.183,69.012 40.183,70.688 52.045,82.55 v2(60.642,82.55)
NetD1_1: D1.1 R27.1 | length 2.8
  Top Layer w0.203: R27.1 D1.1
NetD1_2: D1.2 J2.2 TP19.1 U1.9 | length 124.4
  Top Layer w0.203: U1.9 21.799,45.598 22.464,44.933 28.219,44.933 v2(28.702,44.45) ; v2(55.626,91.44) 55.626,94.488 56.134,94.996 J2.2@56.134,98.171 ; J2.2 J2.2@56.134,98.171 ; TP19.1 83.852,79.661 D1.2 78.613,95.758 65.024,95.758 63.627,97.155 57.15,97.155 J2.2@56.134,98.171
  Bottom Layer w0.203: v2(28.702,44.45) 32.385,48.133 32.385,71.882 33.858,73.355 40.462,73.355 55.626,88.519 v2(55.626,91.44)
NetD2_3: D2.3 R17.2 R19.2 R22.1 | length 26.9
  Top Layer w0.203: R22.1 11.684,28.575 v2(11.811,28.448) ; v2(25.781,31.877) R17.2 27.648,36.068 R19.2
  Top Layer w0.254: D2.3 9.538,29.845 10.058,30.365 R22.1
  Bottom Layer w0.203: v2(11.811,28.448) 18.505,28.448 20.89,30.832 24.736,30.832 v2(25.781,31.877)
NetJ2_3: J2.3 R34.1 U4.7 | length 50
  Top Layer w0.203: U4.7 36.228,87.257 37.338,88.367 38.621,88.367 R34.1 39.612,83.947 40.628,82.931 48.793,82.931 49.733,81.991 49.733,78.257 50.622,77.368 56.439,77.368 57.328,78.257 57.328,95.809 J2.3
NetJ2_5: J2.5 R35.1 U4.8 | length 58.2
  Top Layer w0.203: v2(26.01,90.449) 35.535,90.449 35.941,90.043 35.941,89.637 36.805,88.773 37.084,88.773 ; U4.8 36.068,87.757 37.084,88.773 ; R35.1@39.497,89.547 R35.1 39.612,89.611 38.774,88.773 37.084,88.773
  Bottom Layer w0.203: v2(26.01,90.449) 26.01,95.352 26.848,96.19 46.711,96.19 47.803,97.282 58.499,97.282 J2.5@59.896,95.885
NetQ1_1: Q1.1 R1.1 R25.2 | length 3.8
  Top Layer w0.203: R1.1 R25.2 ; R25.2@12.304,23.48 Q1.1
NetQ4_3: Q4.3 R8.1 R10.1 R11.2 | length 6
  Top Layer w0.203: R10.1 R11.2 11.152,65.278 R8.1 11.32,65.446 Q4.3
NetR11_1: R11.1 TP7.1 U1.19 | length 69.4
  Top Layer w0.203: v2(7.874,64.389) 7.874,65.254 R11.1 R11.1@7.898,65.38 ; v2(16.129,82.042) 18.212,82.042 19.402,80.851 22.4,80.851 23.622,79.629 40.132,79.629 TP7.1 ; v2(19.05,52.197) 20.299,50.948 U1.19
  Bottom Layer w0.203: v2(7.874,64.389) 16.383,64.389 ; v2(16.129,82.042) 16.129,79.248 16.383,78.994 16.383,64.389 ; v2@18.796,52.451 17.193,54.054 17.193,55.274 16.793,55.674 16.64,55.674 16.208,56.105 16.208,56.845 16.383,57.02 16.383,64.389
NetR13_1: R13.1 TP8.1 U1.8 | length 88.7
  Top Layer w0.203: v2(15.215,24.587) 16.358,24.587 17.678,25.908 R13.1 ; U1.8 21.299,45.3 22.387,44.212 v2@23.758,44.212 ; v2(23.774,44.212) v2@23.758,44.212 ; v2@24.359,30.023 24.359,30.099 v2(24.308,30.15) 24.308,31.699 24.13,31.877 24.13,41.351 23.771,41.71 23.771,44.199 v2@23.758,44.212 ; v2(25.4,76.073) 25.4,75.667 25.68,75.387 41.319,75.387 TP8.1
  Bottom Layer w0.203: v2(15.215,24.587) 20.65,30.023 v2@24.359,30.023 ; v2(23.774,44.212) 24.257,44.695 24.257,46.634 23.778,47.113 23.778,47.678 24.057,47.958 24.057,50.441 23.778,50.72 23.778,51.286 24.057,51.565 24.057,65.021 23.778,65.3 23.778,65.866 24.638,66.726 24.638,74.128 24.133,74.633 24.133,75.746 24.46,76.073 v2(25.4,76.073)
NetR14_1: R14.1 TP18.1 U1.7 | length 117.4
  Top Layer w0.203: R14.1 20.66,25.908 23.368,28.616 v2(23.368,41.148) 23.368,42.656 20.799,45.225 U1.7 ; v2(73.152,40.259) 75.565,40.259 76.073,40.767 76.073,74.993 TP18.1
  Bottom Layer w0.203: v2(23.368,41.148) 23.495,41.148 24.765,39.878 72.771,39.878 v2(73.152,40.259)
NetR18_2: R18.2 R31.1 TP11.1 U1.17 | length 89.9
  Top Layer w0.203: v2(20.955,53.086) 20.955,51.943 21.299,51.599 U1.17 ; R18.2@25.146,70.461 25.146,70.968 ; v2(25.781,72.009) 25.781,71.704 25.146,71.069 ; v2(27.813,73.762) 27.813,71.552 27.508,71.247 R31.1 25.425,71.247 ; v2(53.518,90.297) 53.518,81.864 TP11.1 ; 25.146,70.968 25.425,71.247 ; 25.146,70.968 25.146,71.069 ; 25.146,71.069 25.324,71.247 25.425,71.247
  Bottom Layer w0.203: v2(20.955,53.086) 23.654,55.785 23.654,64.854 23.374,65.133 23.374,66.033 24.073,66.732 24.073,73.502 23.622,73.953 23.622,74.574 23.092,75.104 23.092,75.67 23.898,76.476 24.838,76.476 25.117,76.756 25.683,76.756 26.083,76.356 26.083,75.79 25.683,75.39 24.867,75.39 24.816,75.339 24.816,74.521 25.19,74.146 25.19,72.244 25.425,72.009 v2(25.781,72.009) ; v2(27.813,73.762) 36.243,73.762 52.779,90.297 v2(53.518,90.297)
NetR20_1: R20.1 U1.21 | length 3.1
  Top Layer w0.203: R20.1 17.399,51.606 18.325,50.679 18.987,50.679 19.24,50.427 19.24,49.935 U1.21
NetR21_1: R21.1 R23.2 R24.2 R26.2 TP12.1 | length 93.5
  Top Layer w0.254: R26.2 R24.2 R23.2 21.947,17.375 R21.1 v2(23.622,17.399) ; v2(40.259,37.592) v2(40.259,50.165) ; TP12.1 60.452,78.867 v2(61.468,77.851)
  Bottom Layer w0.254: v2(23.622,17.399) 30.734,17.399 31.623,18.288 31.623,25.654 40.259,34.29 v2(40.259,37.592) ; v2(40.259,50.165) 40.259,51.748 46.922,51.748 62.357,67.183 62.357,77.343 61.849,77.851 v2(61.468,77.851)
NetR23_1: R23.1 U1.10 | length 44.6
  Top Layer w0.203: v2(20.32,19.685) R23.1 R23.1@20.345,18.875 ; U1.10 22.299,45.745 22.705,45.339 29.21,45.339 30.48,44.069 30.48,20.193 v2(30.099,19.812)
  Bottom Layer w0.203: v2(20.32,19.685) 29.972,19.685 v2(30.099,19.812)
NetR30_1: R30.1 R32.2 TP10.1 U1.13 | length 97.3
  Top Layer w0.203: R32.2 22.201,72.747 22.582,73.128 R30.1 23.749,73.914 ; v2(23.089,77.445) 23.089,74.701 23.749,74.041 23.749,73.914 ; v2(23.089,93.726) 46.838,93.726 51.968,88.595 51.968,79.508 TP10.1 ; U1.13 24.004,48.896 25.146,50.038 v2(25.146,53.899) ; v2(28.499,57.252) 28.499,74.143 28.067,74.574 24.409,74.574 23.749,73.914
  Bottom Layer w0.203: v2(23.089,77.445) v2(23.089,93.726) ; v2(25.146,53.899) v2(28.499,57.252)
NetR33_1: R33.1 U3.8 | length 2.5
  Top Layer w0.203: R33.1 22.149,89.599 U3.8
NetR33_2: R33.2 U3.1 | length 2.5
  Top Layer w0.203: U3.1 17.221,89.599 R33.2
NetR36_1: R36.1 R37.2 U4.4 | length 9.3
  Top Layer w0.203: R36.1 28.043,86.614 28.297,86.868 29.404,86.868 29.404,87.021 29.58,87.198 30.192,87.198 U4.4 30.284,87.224 30.912,87.224 31.115,87.427 31.115,89.078 30.912,89.281 R37.2
NetU3_5: U3.5 U4.2 | length 9.2
  Top Layer w0.203: U3.5 23.767,85.725 26.035,87.993 28.319,87.993 28.583,88.257 U4.2
NetU3_6: U3.6 U4.1 | length 8.8
  Top Layer w0.203: U3.6 24.384,86.995 25.788,88.399 28.15,88.399 28.509,88.758 U4.1
ON: J1.8 J2.4 | length 114
  Bottom Layer w0.254: J1.8 51.874,8.099 60.296,8.099 74.752,22.555 74.752,86.182 63.906,97.028 60.071,97.028 J2.4
TPST4: J1.3 U2.4 | length 47.9
  Top Layer w1.27: J1.3@34.12,8.099 36.504,5.715 60.739,5.715 62.155,7.131 64.789,7.131 67.056,9.398 74.549,9.398 76.581,11.43 U2.4
VBAT: C14.2 C15.2 C16.2 D2.2 J1.5 Q4.4 Q4.7 R15.1 R16.2 R36.2 U3.7 | length 20.3
  Top Layer w0.254: R15.1@13.208,59.088 13.208,57.912 22.987,57.912 23.035,57.864 23.035,56.182 24.511,56.182 R16.2 ; U3.7 23.749,88.265 v2(23.876,88.138)
  Bottom Layer w0.254: v2(23.876,88.138) 24.892,87.122 v2(24.892,84.836)
  other v1: 5.08,30.226 5.969,30.226 5.08,31.115 5.969,31.115 5.08,32.004 5.969,32.004 5.08,32.893 5.969,32.893 11.938,61.341 12.827,61.341 13.716,61.341 14.605,61.341 15.494,61.341 11.938,62.23 12.827,62.23 13.716,62.23 14.605,62.23 15.494,62.23 11.938,63.119 12.827,63.119 13.716,63.119 14.605,63.119 15.494,63.119 24.892,81.28 25.781,81.28 24.892,82.169 25.781,82.169 24.892,83.058 25.781,83.058 24.892,83.947 25.781,83.947
VREF: C19.2 R21.2 R27.2 R30.2 R31.2 TP16.1 U1.12 U1.14 | length 186.9
  Top Layer w0.203: R21.2 23.011,18.899 v2(23.114,18.796) ; U1.14 22.799,50.571 23.23,51.003 v2(24.46,51.003) ; v2(24.46,47.396) U1.12 ; v2(24.46,65.583) 24.46,71.831 25.249,72.62 R30.2 26.67,73.128 R31.2@26.797,73.001 ; C19.2 23.436,47.204 U1.12 ; v2(26.797,73.558) R31.2@26.797,73.001 ; v2@30.861,18.923 30.883,18.945 30.883,48.568 29.871,49.581 25.273,49.581 23.245,47.552 U1.12 ; v2(58.115,92.456) 59.614,90.957 59.614,78.054 61.366,76.302 66.04,76.302 ; TP16.1 71.603,78.867 69.037,76.302 66.04,76.302 ; R27.2@83.439,84.988 R27.2 68.834,85.09 66.04,82.296 66.04,76.302 ; R31.2@26.797,73.001 R31.2 26.797,72.747 R31.2@26.797,73.001
  Bottom Layer w0.203: v2(23.114,18.796) v2(30.861,18.796) ; v2(24.46,47.396) v2(24.46,51.003) v2(24.46,65.583) ; v2(26.797,73.558) 26.797,90.856 28.397,92.456 v2(58.115,92.456)
VSYS: C1.1 C7.2 C8.2 J1.4 Q4.1 Q4.2 Q4.5 Q4.6 Q4.8 R2.1 R3.2 R8.2 U1.2 U1.3 U2.3 | length 7
  Top Layer w0.203: R2.1@18.288,38.1 19.812,38.1 19.812,40.894 18.288,40.894 R3.2 ; U1.2 U1.3
  other v1: 69.215,13.462 70.104,13.462 70.993,13.462 69.215,14.351 70.104,14.351 70.993,14.351 69.215,15.24 70.104,15.24 70.993,15.24 15.621,37.719 16.51,37.719 17.399,37.719 16.51,38.608 17.399,38.608 15.621,39.497 16.51,39.497 17.399,39.497 12.065,72.263 12.954,72.263 13.843,72.263 12.065,73.152 12.954,73.152 13.843,73.152 12.065,74.041 12.954,74.041 13.843,74.041 12.065,74.93 12.954,74.93 13.843,74.93 12.065,75.819 12.954,75.819 13.843,75.819
  other v4: 15.621,38.608
pads on no net: P1. P1.2 P1.3 P1.6 P1.7 P1.8 U2.2 U2.5 U2.6 U2.7 U2.8 U2.9

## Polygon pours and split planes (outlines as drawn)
GND on Bottom Layer "Bottom_Layer_AGND" (solid, pour order 26): 0.635,0.635 99.06,0.635 99.06,99.06 0.635,99.06 0.635,0.635
DCGND on Bottom GND "Bottom GND-DCGND" (solid, pour order 25): 99.695,76.835 39.116,76.835 39.116,67.818 86.995,67.818 86.995,51.054 87.122,5.207 39.497,5.207 39.497,15.875 0.635,15.875 0.635,0.635 99.695,0.635
GND on Bottom GND "Bottom GND-AGND" (solid, pour order 41): 0.635,0.635 0.635,99.695 99.695,99.695 99.695,0.635
VSYS on Top GND "TOP GND-VSYS" (solid, pour order 24): 0.635,0.635 0.635,99.695 99.06,99.695 99.06,0.635
15V on Top GND "TOP GND-15V" (solid, pour order 23): 7.747,36.449 82.55,36.449 82.55,17.78 7.747,17.78 7.747,36.449
VBAT on Top GND "TOP GND-VBAT" (solid, pour order 22): 0.635,99.695 31.115,99.695 30.988,99.568 30.988,79.248 7.747,79.248 7.62,79.375 7.62,65.786 21.082,65.786 21.336,65.532 21.209,65.405 21.209,46.482 7.62,46.482 7.62,17.145 23.749,17.145 23.749,6.096 39.497,6.096 39.497,10.795 64.643,10.795 64.643,0.635 0.635,0.635
AGND on Top Layer "Top Layer-AGND" (solid, pour order 40): 1.186,-0.171 99.611,-0.171 99.695,99.568 1.016,99.441
15V on Top Layer "15V" (solid, pour order 36): 17.002,26.584 29.304,26.584 29.464,26.371 29.464,20.193 25.527,20.193 25.527,16.637 14.859,16.637 14.859,20.32 14.765,26.584 16.682,26.584 16.842,26.797
15V on Top Layer "15V" (solid, pour order 34): 16.365,36.289 16.492,36.289 16.492,31.296 16.873,30.891 16.873,29.812 13.444,29.812 13.444,30.891 8.618,30.891 8.618,36.289 16.492,36.289
VSYS on Top Layer "VSYS" (solid, pour order 38): 68.072,18.825 82.271,18.825 82.931,18.431 82.931,9.087 68.402,9.087 68.072,8.89 68.072,18.923
VBAT on Top Layer "VBAT" (solid, pour order 37): 23.622,87.884 29.307,87.884 29.591,87.593 29.591,79.883 23.622,79.883
VBAT on Top Layer "VBAT" (solid, pour order 35): 7.158,33.703 8.474,33.703 8.618,33.33 8.618,29.473 7.272,29.473 7.25,29.416 7.158,29.178 7.158,24.892 4.029,24.892 3.937,25.13 3.937,36.322 7.158,36.322 7.158,33.941 7.158,33.703
VSYS on Top Layer "VSYS" (solid, pour order 33): 10.16,65.913 16.764,65.786 16.764,78.105 8.001,78.105 8.001,68.199 10.16,68.199
NetC5_2 on Top Layer "NetC5_2" (solid, pour order 32): 20.574,39.37 22.479,39.37 22.479,32.153 19.812,32.131 19.812,35.687 20.574,35.687
VSYS on Top Layer "VSYS" (solid, pour order 31): 17.249,47.244 19.05,47.244 19.05,45.085 18.288,45.085 18.288,43.942 16.891,43.942 16.934,40.991 19.431,40.958 19.431,36.449 14.605,36.449 14.626,46.428 17.249,46.428
NetC6_2 on Top Layer "NetC6_2" (solid, pour order 30): 16.383,35.941 20.32,35.941 20.32,26.797 18.773,26.797 18.773,33.655 16.383,33.655 16.383,35.941
VBAT on Top Layer "VBAT" (solid, pour order 29): 8.989,58.214 8.989,64.104 10.414,64.104 10.414,65.978 20.8,65.978 20.8,58.214
NetC13_2 on Top Layer "NetC13_2" (solid, pour order 28): 18.034,48.593 18.034,49.149 8.89,49.149 8.89,46.228 16.412,46.228 16.412,47.117 18.034,47.117 18.034,47.619 16.412,47.619 16.412,48.593
NetC18_1 on Top Layer "NetC18_1" (solid, pour order 27): 9.012,51.054 9.012,57.15 13.843,57.15 13.843,51.054

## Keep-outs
Keep-Out Layer:
  circle w0.254: c3,3 r2.54
  circle w0.254: c97,3 r2.54
  circle w0.254: c97,97 r2.54
  circle w0.254: c3,97 r2.54
  region: 0,99.949 2.794,99.949 2.794,0 0,0
  region: 97.028,99.822 99.822,99.822 99.822,-0.127 97.028,-0.127
  lines w0.254: 2.794,0 2.794,99.949 ; 96.901,0 96.901,99.949 ; 0,0 99.949,0 99.949,99.949 0,99.949 0,0

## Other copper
Top Layer:
  pour cut-out: 20.447,57.023 21.844,57.023 21.844,53.721 20.447,53.721
  pour cut-out: 30.099,82.804 33.655,82.804 33.655,80.01 30.099,80.01

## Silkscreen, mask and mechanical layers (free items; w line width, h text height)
Mechanical 16:
  drawing of 1874 lines, arcs and shapes, not listed
  text "1" at 18.593,168.91 h1.78
  text "2" at 91.237,168.91 h1.78
  text "3" at 164.389,168.91 h1.78
  text "4" at 237.287,168.91 h1.78
  text "A" at -15.748,145.898 h1.78
  text "A" at 271.272,145.898 h1.78
  text "B" at -15.748,97.841 h1.78
  text "B" at 271.272,97.841 h1.78
  text "C" at -15.748,49.327 h1.78
  text "C" at 271.272,49.327 h1.78
  text "ENGINEER:" at 156.337,12.319 h1.14
  text "TITLE:" at 194.437,12.319 h1.14
  text "PCB DESIGNER:" at 156.337,4.826 h1.14
  text "D" at -15.748,1.321 h1.78
  text "D" at 271.272,1.321 h1.78
  text "DATE:" at 156.337,-2.921 h1.14
  text "PART NO.:" at 194.437,-2.921 h1.14
  text "REV:" at 247.777,-2.921 h1.14
  text "Altium Limited" at 123.317,-5.461 h1.78
  text ".PRINT_DATE" at 157.607,-5.969 h1.78
  text "12a Rodborough Rd" at 123.317,-8.001 h1.78
  text "Frenchs Forest" at 123.317,-10.541 h1.78
  text "FILE NAME:" at 156.337,-10.541 h1.14
  text "DWG NO:" at 194.437,-10.541 h1.14
  text "SCALE:" at 247.777,-10.541 h1.14
  text "NSW 2086" at 123.317,-13.081 h1.78
  text ".PCB_FILE_NAME_NO_PATH" at 157.607,-13.589 h1.78
  text "1" at 18.593,-19.05 h1.78
  text "2" at 91.237,-19.05 h1.78
  text "3" at 164.389,-19.05 h1.78
  text "4" at 237.287,-19.05 h1.78

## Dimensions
-0.127,100.203 to 2.921,100.457 on Mechanical 2
99.949,100.203 to 96.901,100.203 on Mechanical 2
-0.127,100.203 to 99.949,100.203 on Mechanical 2
0,99.949 to 0,0 on Mechanical 2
